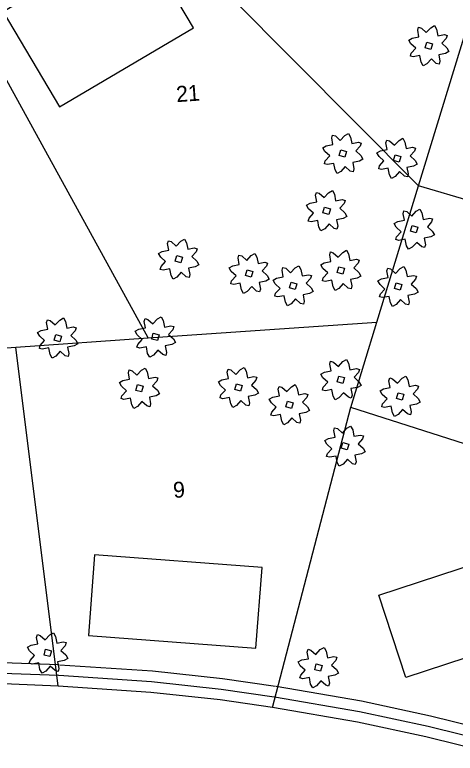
# Model space of a CAD drawing. Extents: x 1810019 to 1811399, y 1074962 to 1076105.
# Drawn here: x 1810473.9 to 1810639.9, y 1075253.3 to 1075531.7 of the extents above; entities that cross this region are included whole.
import ezdxf

# ---------------------------------------------------------------- set-up
doc = ezdxf.new("R2010")
doc.units = 0
for name, color, linetype in [('Environmental-New trees', 7, 'Continuous'), ('Property-Buildings', 7, 'Continuous'), ('Roadway-Land lines', 7, 'Continuous'), ('Roadway-Sidewalks', 7, 'Continuous'), ('Text-Property owner', 7, 'Continuous')]:
    doc.layers.add(name, color=color, linetype=linetype)

msp = doc.modelspace()

# ---------------------------------------------------------------- linework, layer by layer
at = {"layer": 'Environmental-New trees'}
for points in [[(1810623, 1075516.16), (1810623.31, 1075517.24), (1810625, 1075519.1), (1810623.14, 1075520.79), (1810622.36, 1075522.18), (1810623.72, 1075522.94), (1810626.22, 1075523.43), (1810625.75, 1075525.9), (1810626.06, 1075526.99), (1810627.14, 1075526.68), (1810629, 1075524.99), (1810630.69, 1075526.85), (1810632.08, 1075527.63), (1810632.86, 1075526.24), (1810633.33, 1075523.77), (1810635.8, 1075524.24), (1810636.89, 1075523.94), (1810636.52, 1075522.78), (1810634.89, 1075520.99), (1810636.75, 1075519.3), (1810637.53, 1075517.91), (1810636.18, 1075517.15), (1810633.67, 1075516.66), (1810634.14, 1075514.19), (1810633.84, 1075513.1), (1810632.75, 1075513.41), (1810630.89, 1075515.1), (1810629.2, 1075513.24), (1810627.81, 1075512.46), (1810627.03, 1075513.85), (1810626.56, 1075516.32), (1810624.09, 1075515.85)], [(1810629.17, 1075521.43), (1810631.33, 1075520.82), (1810630.72, 1075518.66), (1810628.56, 1075519.27)], [(1810590.59, 1075475.55), (1810590.89, 1075476.63), (1810592.58, 1075478.49), (1810590.72, 1075480.18), (1810589.94, 1075481.57), (1810591.3, 1075482.33), (1810593.8, 1075482.82), (1810593.33, 1075485.29), (1810593.64, 1075486.38), (1810594.72, 1075486.07), (1810596.58, 1075484.38), (1810598.27, 1075486.24), (1810599.66, 1075487.02), (1810600.44, 1075485.63), (1810600.91, 1075483.16), (1810603.38, 1075483.63), (1810604.47, 1075483.33), (1810604.1, 1075482.17), (1810602.47, 1075480.38), (1810604.33, 1075478.69), (1810605.11, 1075477.3), (1810603.76, 1075476.54), (1810601.25, 1075476.05), (1810601.72, 1075473.58), (1810601.42, 1075472.49), (1810600.33, 1075472.8), (1810598.47, 1075474.49), (1810596.78, 1075472.63), (1810595.39, 1075471.85), (1810594.61, 1075473.24), (1810594.14, 1075475.71), (1810591.67, 1075475.24)], [(1810611.04, 1075473.67), (1810611.34, 1075474.75), (1810613.03, 1075476.62), (1810611.17, 1075478.31), (1810610.39, 1075479.7), (1810611.75, 1075480.45), (1810614.25, 1075480.95), (1810613.78, 1075483.42), (1810614.09, 1075484.5), (1810615.17, 1075484.2), (1810617.03, 1075482.5), (1810618.72, 1075484.36), (1810620.11, 1075485.14), (1810620.89, 1075483.75), (1810621.36, 1075481.28), (1810623.83, 1075481.76), (1810624.92, 1075481.45), (1810624.55, 1075480.29), (1810622.92, 1075478.51), (1810624.78, 1075476.81), (1810625.56, 1075475.42), (1810624.21, 1075474.67), (1810621.7, 1075474.17), (1810622.17, 1075471.7), (1810621.87, 1075470.62), (1810620.78, 1075470.92), (1810618.92, 1075472.62), (1810617.23, 1075470.76), (1810615.84, 1075469.98), (1810615.06, 1075471.37), (1810614.59, 1075473.84), (1810612.12, 1075473.37)], [(1810596.75, 1075480.82), (1810598.91, 1075480.21), (1810598.3, 1075478.05), (1810596.14, 1075478.66)], [(1810617.2, 1075478.95), (1810619.36, 1075478.34), (1810618.75, 1075476.17), (1810616.59, 1075476.78)], [(1810584.5, 1075453.94), (1810584.8, 1075455.03), (1810586.5, 1075456.89), (1810584.64, 1075458.58), (1810583.86, 1075459.97), (1810585.21, 1075460.73), (1810587.72, 1075461.22), (1810587.25, 1075463.69), (1810587.55, 1075464.77), (1810588.63, 1075464.47), (1810590.49, 1075462.78), (1810592.19, 1075464.64), (1810593.58, 1075465.42), (1810594.35, 1075464.03), (1810594.83, 1075461.56), (1810597.3, 1075462.03), (1810598.38, 1075461.72), (1810598.01, 1075460.57), (1810596.38, 1075458.78), (1810598.24, 1075457.09), (1810599.02, 1075455.7), (1810597.67, 1075454.94), (1810595.16, 1075454.45), (1810595.64, 1075451.98), (1810595.33, 1075450.89), (1810594.25, 1075451.2), (1810592.39, 1075452.89), (1810590.69, 1075451.03), (1810589.3, 1075450.25), (1810588.53, 1075451.64), (1810588.05, 1075454.11), (1810585.58, 1075453.64)], [(1810590.66, 1075459.22), (1810592.83, 1075458.61), (1810592.22, 1075456.45), (1810590.05, 1075457.06)], [(1810617.5, 1075446.98), (1810617.81, 1075448.06), (1810619.5, 1075449.92), (1810617.64, 1075451.62), (1810616.86, 1075453), (1810618.21, 1075453.76), (1810620.72, 1075454.25), (1810620.25, 1075456.73), (1810620.55, 1075457.81), (1810621.63, 1075457.5), (1810623.5, 1075455.81), (1810625.19, 1075457.67), (1810626.58, 1075458.45), (1810627.36, 1075457.06), (1810627.83, 1075454.59), (1810630.3, 1075455.06), (1810631.38, 1075454.76), (1810631.01, 1075453.6), (1810629.38, 1075451.81), (1810631.25, 1075450.12), (1810632.02, 1075448.73), (1810630.67, 1075447.97), (1810628.16, 1075447.48), (1810628.64, 1075445.01), (1810628.33, 1075443.93), (1810627.25, 1075444.23), (1810625.39, 1075445.92), (1810623.69, 1075444.06), (1810622.31, 1075443.29), (1810621.53, 1075444.67), (1810621.05, 1075447.15), (1810618.58, 1075446.67)], [(1810623.66, 1075452.26), (1810625.83, 1075451.65), (1810625.22, 1075449.48), (1810623.05, 1075450.09)], [(1810528.75, 1075435.71), (1810529.06, 1075436.79), (1810530.75, 1075438.66), (1810528.89, 1075440.35), (1810528.11, 1075441.74), (1810529.46, 1075442.49), (1810531.97, 1075442.99), (1810531.5, 1075445.46), (1810531.8, 1075446.54), (1810532.89, 1075446.24), (1810534.75, 1075444.54), (1810536.44, 1075446.4), (1810537.83, 1075447.18), (1810538.61, 1075445.79), (1810539.08, 1075443.32), (1810541.55, 1075443.8), (1810542.63, 1075443.49), (1810542.27, 1075442.33), (1810540.64, 1075440.55), (1810542.5, 1075438.85), (1810543.27, 1075437.47), (1810541.92, 1075436.71), (1810539.42, 1075436.21), (1810539.89, 1075433.74), (1810539.58, 1075432.66), (1810538.5, 1075432.97), (1810536.64, 1075434.66), (1810534.95, 1075432.8), (1810533.56, 1075432.02), (1810532.78, 1075433.41), (1810532.31, 1075435.88), (1810529.84, 1075435.41)], [(1810589.82, 1075431.46), (1810590.12, 1075432.54), (1810591.82, 1075434.4), (1810589.96, 1075436.1), (1810589.18, 1075437.48), (1810590.53, 1075438.24), (1810593.04, 1075438.74), (1810592.57, 1075441.21), (1810592.87, 1075442.29), (1810593.95, 1075441.99), (1810595.81, 1075440.29), (1810597.51, 1075442.15), (1810598.9, 1075442.93), (1810599.67, 1075441.54), (1810600.15, 1075439.07), (1810602.62, 1075439.54), (1810603.7, 1075439.24), (1810603.33, 1075438.08), (1810601.7, 1075436.29), (1810603.56, 1075434.6), (1810604.34, 1075433.21), (1810602.99, 1075432.46), (1810600.48, 1075431.96), (1810600.95, 1075429.49), (1810600.65, 1075428.41), (1810599.57, 1075428.71), (1810597.71, 1075430.41), (1810596.01, 1075428.55), (1810594.62, 1075427.77), (1810593.85, 1075429.16), (1810593.37, 1075431.63), (1810590.9, 1075431.15)], [(1810534.92, 1075440.99), (1810537.08, 1075440.38), (1810536.47, 1075438.21), (1810534.31, 1075438.82)], [(1810555.31, 1075430.3), (1810555.61, 1075431.38), (1810557.3, 1075433.25), (1810555.44, 1075434.94), (1810554.67, 1075436.33), (1810556.02, 1075437.08), (1810558.52, 1075437.58), (1810558.05, 1075440.05), (1810558.36, 1075441.13), (1810559.44, 1075440.83), (1810561.3, 1075439.13), (1810562.99, 1075440.99), (1810564.38, 1075441.77), (1810565.16, 1075440.38), (1810565.63, 1075437.91), (1810568.11, 1075438.39), (1810569.19, 1075438.08), (1810568.82, 1075436.92), (1810567.19, 1075435.14), (1810569.05, 1075433.44), (1810569.83, 1075432.06), (1810568.48, 1075431.3), (1810565.97, 1075430.8), (1810566.44, 1075428.33), (1810566.14, 1075427.25), (1810565.05, 1075427.55), (1810563.19, 1075429.25), (1810561.5, 1075427.39), (1810560.11, 1075426.61), (1810559.33, 1075428), (1810558.86, 1075430.47), (1810556.39, 1075430)], [(1810571.86, 1075425.64), (1810572.17, 1075426.72), (1810573.86, 1075428.58), (1810572, 1075430.27), (1810571.22, 1075431.66), (1810572.57, 1075432.42), (1810575.08, 1075432.91), (1810574.61, 1075435.38), (1810574.91, 1075436.47), (1810576, 1075436.16), (1810577.86, 1075434.47), (1810579.55, 1075436.33), (1810580.94, 1075437.11), (1810581.72, 1075435.72), (1810582.19, 1075433.25), (1810584.66, 1075433.72), (1810585.74, 1075433.42), (1810585.38, 1075432.26), (1810583.75, 1075430.47), (1810585.61, 1075428.78), (1810586.38, 1075427.39), (1810585.03, 1075426.63), (1810582.53, 1075426.14), (1810583, 1075423.67), (1810582.69, 1075422.59), (1810581.61, 1075422.89), (1810579.75, 1075424.58), (1810578.06, 1075422.72), (1810576.67, 1075421.94), (1810575.89, 1075423.33), (1810575.42, 1075425.8), (1810572.95, 1075425.33)], [(1810595.98, 1075436.74), (1810598.15, 1075436.13), (1810597.54, 1075433.96), (1810595.37, 1075434.57)], [(1810611.41, 1075425.37), (1810611.72, 1075426.46), (1810613.41, 1075428.32), (1810611.55, 1075430.01), (1810610.77, 1075431.4), (1810612.13, 1075432.16), (1810614.63, 1075432.65), (1810614.16, 1075435.12), (1810614.47, 1075436.21), (1810615.55, 1075435.9), (1810617.41, 1075434.21), (1810619.1, 1075436.07), (1810620.49, 1075436.85), (1810621.27, 1075435.46), (1810621.74, 1075432.99), (1810624.21, 1075433.46), (1810625.3, 1075433.15), (1810624.93, 1075432), (1810623.3, 1075430.21), (1810625.16, 1075428.52), (1810625.94, 1075427.13), (1810624.58, 1075426.37), (1810622.08, 1075425.88), (1810622.55, 1075423.41), (1810622.25, 1075422.32), (1810621.16, 1075422.63), (1810619.3, 1075424.32), (1810617.61, 1075422.46), (1810616.22, 1075421.68), (1810615.44, 1075423.07), (1810614.97, 1075425.54), (1810612.5, 1075425.07)], [(1810561.47, 1075435.58), (1810563.64, 1075434.97), (1810563.02, 1075432.8), (1810560.86, 1075433.41)], [(1810578.03, 1075430.91), (1810580.19, 1075430.3), (1810579.58, 1075428.14), (1810577.41, 1075428.75)], [(1810617.58, 1075430.65), (1810619.74, 1075430.04), (1810619.13, 1075427.88), (1810616.97, 1075428.49)], [(1810483.15, 1075405.94), (1810483.45, 1075407.02), (1810485.15, 1075408.88), (1810483.29, 1075410.57), (1810482.51, 1075411.96), (1810483.86, 1075412.72), (1810486.37, 1075413.21), (1810485.89, 1075415.68), (1810486.2, 1075416.77), (1810487.28, 1075416.46), (1810489.14, 1075414.77), (1810490.84, 1075416.63), (1810492.23, 1075417.41), (1810493, 1075416.02), (1810493.48, 1075413.55), (1810495.95, 1075414.02), (1810497.03, 1075413.72), (1810496.66, 1075412.56), (1810495.03, 1075410.77), (1810496.89, 1075409.08), (1810497.67, 1075407.69), (1810496.32, 1075406.93), (1810493.81, 1075406.44), (1810494.28, 1075403.97), (1810493.98, 1075402.88), (1810492.9, 1075403.19), (1810491.03, 1075404.88), (1810489.34, 1075403.02), (1810487.95, 1075402.24), (1810487.18, 1075403.63), (1810486.7, 1075406.1), (1810484.23, 1075405.63)], [(1810519.94, 1075406.36), (1810520.25, 1075407.44), (1810521.94, 1075409.3), (1810520.08, 1075411), (1810519.3, 1075412.39), (1810520.66, 1075413.14), (1810523.16, 1075413.64), (1810522.69, 1075416.11), (1810522.99, 1075417.19), (1810524.08, 1075416.89), (1810525.94, 1075415.19), (1810527.63, 1075417.05), (1810529.02, 1075417.83), (1810529.8, 1075416.44), (1810530.27, 1075413.97), (1810532.74, 1075414.44), (1810533.83, 1075414.14), (1810533.46, 1075412.98), (1810531.83, 1075411.2), (1810533.69, 1075409.5), (1810534.47, 1075408.11), (1810533.11, 1075407.36), (1810530.61, 1075406.86), (1810531.08, 1075404.39), (1810530.77, 1075403.31), (1810529.69, 1075403.61), (1810527.83, 1075405.31), (1810526.14, 1075403.45), (1810524.75, 1075402.67), (1810523.97, 1075404.06), (1810523.5, 1075406.53), (1810521.03, 1075406.06)], [(1810526.11, 1075411.64), (1810528.27, 1075411.03), (1810527.66, 1075408.86), (1810525.5, 1075409.47)], [(1810489.31, 1075411.21), (1810491.48, 1075410.6), (1810490.87, 1075408.44), (1810488.7, 1075409.05)], [(1810589.86, 1075390.25), (1810590.17, 1075391.34), (1810591.86, 1075393.2), (1810590, 1075394.89), (1810589.22, 1075396.28), (1810590.58, 1075397.04), (1810593.08, 1075397.53), (1810592.61, 1075400), (1810592.92, 1075401.08), (1810594, 1075400.78), (1810595.86, 1075399.08), (1810597.55, 1075400.95), (1810598.94, 1075401.72), (1810599.72, 1075400.34), (1810600.19, 1075397.86), (1810602.66, 1075398.34), (1810603.75, 1075398.03), (1810603.38, 1075396.88), (1810601.75, 1075395.09), (1810603.61, 1075393.39), (1810604.39, 1075392.01), (1810603.03, 1075391.25), (1810600.53, 1075390.76), (1810601, 1075388.28), (1810600.7, 1075387.2), (1810599.61, 1075387.51), (1810597.75, 1075389.2), (1810596.06, 1075387.34), (1810594.67, 1075386.56), (1810593.89, 1075387.95), (1810593.42, 1075390.42), (1810590.95, 1075389.95)], [(1810513.95, 1075387.01), (1810514.26, 1075388.09), (1810515.95, 1075389.95), (1810514.09, 1075391.64), (1810513.31, 1075393.03), (1810514.66, 1075393.79), (1810517.17, 1075394.28), (1810516.7, 1075396.75), (1810517, 1075397.84), (1810518.09, 1075397.53), (1810519.95, 1075395.84), (1810521.64, 1075397.7), (1810523.03, 1075398.48), (1810523.81, 1075397.09), (1810524.28, 1075394.62), (1810526.75, 1075395.09), (1810527.83, 1075394.79), (1810527.46, 1075393.63), (1810525.84, 1075391.84), (1810527.7, 1075390.15), (1810528.47, 1075388.76), (1810527.12, 1075388), (1810524.61, 1075387.51), (1810525.09, 1075385.04), (1810524.78, 1075383.95), (1810523.7, 1075384.26), (1810521.84, 1075385.95), (1810520.14, 1075384.09), (1810518.76, 1075383.31), (1810517.98, 1075384.7), (1810517.51, 1075387.17), (1810515.03, 1075386.7)], [(1810551.25, 1075387.29), (1810551.55, 1075388.37), (1810553.25, 1075390.23), (1810551.38, 1075391.93), (1810550.61, 1075393.32), (1810551.96, 1075394.07), (1810554.47, 1075394.57), (1810553.99, 1075397.04), (1810554.3, 1075398.12), (1810555.38, 1075397.82), (1810557.24, 1075396.12), (1810558.94, 1075397.98), (1810560.32, 1075398.76), (1810561.1, 1075397.37), (1810561.57, 1075394.9), (1810564.05, 1075395.37), (1810565.13, 1075395.07), (1810564.76, 1075393.91), (1810563.13, 1075392.13), (1810564.99, 1075390.43), (1810565.77, 1075389.04), (1810564.42, 1075388.29), (1810561.91, 1075387.79), (1810562.38, 1075385.32), (1810562.08, 1075384.24), (1810560.99, 1075384.54), (1810559.13, 1075386.24), (1810557.44, 1075384.38), (1810556.05, 1075383.6), (1810555.27, 1075384.99), (1810554.8, 1075387.46), (1810552.33, 1075386.98)], [(1810596.03, 1075395.53), (1810598.19, 1075394.92), (1810597.58, 1075392.75), (1810595.42, 1075393.36)], [(1810612.18, 1075383.97), (1810612.48, 1075385.05), (1810614.18, 1075386.91), (1810612.32, 1075388.6), (1810611.54, 1075389.99), (1810612.89, 1075390.75), (1810615.4, 1075391.24), (1810614.93, 1075393.71), (1810615.23, 1075394.8), (1810616.31, 1075394.49), (1810618.17, 1075392.8), (1810619.87, 1075394.66), (1810621.26, 1075395.44), (1810622.03, 1075394.05), (1810622.51, 1075391.58), (1810624.98, 1075392.05), (1810626.06, 1075391.74), (1810625.69, 1075390.59), (1810624.06, 1075388.8), (1810625.92, 1075387.11), (1810626.7, 1075385.72), (1810625.35, 1075384.96), (1810622.84, 1075384.47), (1810623.32, 1075382), (1810623.01, 1075380.91), (1810621.93, 1075381.22), (1810620.07, 1075382.91), (1810618.37, 1075381.05), (1810616.98, 1075380.27), (1810616.21, 1075381.66), (1810615.73, 1075384.13), (1810613.26, 1075383.66)], [(1810520.11, 1075392.28), (1810522.28, 1075391.67), (1810521.67, 1075389.51), (1810519.5, 1075390.12)], [(1810557.41, 1075392.57), (1810559.58, 1075391.96), (1810558.97, 1075389.79), (1810556.8, 1075390.4)], [(1810570.45, 1075380.8), (1810570.76, 1075381.88), (1810572.45, 1075383.74), (1810570.59, 1075385.44), (1810569.81, 1075386.83), (1810571.16, 1075387.58), (1810573.67, 1075388.08), (1810573.2, 1075390.55), (1810573.5, 1075391.63), (1810574.59, 1075391.33), (1810576.45, 1075389.63), (1810578.14, 1075391.49), (1810579.53, 1075392.27), (1810580.31, 1075390.88), (1810580.78, 1075388.41), (1810583.25, 1075388.88), (1810584.34, 1075388.58), (1810583.97, 1075387.42), (1810582.34, 1075385.63), (1810584.2, 1075383.94), (1810584.98, 1075382.55), (1810583.62, 1075381.8), (1810581.12, 1075381.3), (1810581.59, 1075378.83), (1810581.28, 1075377.75), (1810580.2, 1075378.05), (1810578.34, 1075379.75), (1810576.65, 1075377.89), (1810575.26, 1075377.11), (1810574.48, 1075378.5), (1810574.01, 1075380.97), (1810571.54, 1075380.49)], [(1810618.34, 1075389.24), (1810620.51, 1075388.63), (1810619.9, 1075386.47), (1810617.73, 1075387.08)], [(1810576.62, 1075386.08), (1810578.78, 1075385.47), (1810578.17, 1075383.3), (1810576.01, 1075383.91)], [(1810591.4, 1075365.19), (1810591.71, 1075366.27), (1810593.4, 1075368.13), (1810591.54, 1075369.82), (1810590.76, 1075371.21), (1810592.11, 1075371.97), (1810594.62, 1075372.46), (1810594.15, 1075374.93), (1810594.45, 1075376.02), (1810595.54, 1075375.71), (1810597.4, 1075374.02), (1810599.09, 1075375.88), (1810600.48, 1075376.66), (1810601.26, 1075375.27), (1810601.73, 1075372.8), (1810604.2, 1075373.27), (1810605.29, 1075372.96), (1810604.92, 1075371.81), (1810603.29, 1075370.02), (1810605.15, 1075368.33), (1810605.93, 1075366.94), (1810604.57, 1075366.18), (1810602.07, 1075365.69), (1810602.54, 1075363.22), (1810602.23, 1075362.13), (1810601.15, 1075362.44), (1810599.29, 1075364.13), (1810597.6, 1075362.27), (1810596.21, 1075361.49), (1810595.43, 1075362.88), (1810594.96, 1075365.35), (1810592.49, 1075364.88)], [(1810597.57, 1075370.46), (1810599.73, 1075369.85), (1810599.12, 1075367.69), (1810596.96, 1075368.3)], [(1810479.37, 1075287.22), (1810479.67, 1075288.31), (1810481.37, 1075290.17), (1810479.5, 1075291.86), (1810478.73, 1075293.25), (1810480.08, 1075294.01), (1810482.59, 1075294.5), (1810482.11, 1075296.97), (1810482.42, 1075298.05), (1810483.5, 1075297.75), (1810485.36, 1075296.06), (1810487.06, 1075297.92), (1810488.44, 1075298.69), (1810489.22, 1075297.31), (1810489.69, 1075294.84), (1810492.17, 1075295.31), (1810493.25, 1075295), (1810492.88, 1075293.85), (1810491.25, 1075292.06), (1810493.11, 1075290.37), (1810493.89, 1075288.98), (1810492.54, 1075288.22), (1810490.03, 1075287.73), (1810490.5, 1075285.25), (1810490.2, 1075284.17), (1810489.11, 1075284.48), (1810487.25, 1075286.17), (1810485.56, 1075284.31), (1810484.17, 1075283.53), (1810483.39, 1075284.92), (1810482.92, 1075287.39), (1810480.45, 1075286.92)], [(1810485.53, 1075292.5), (1810487.7, 1075291.89), (1810487.09, 1075289.72), (1810484.92, 1075290.33)], [(1810581.36, 1075281.69), (1810581.67, 1075282.77), (1810583.36, 1075284.63), (1810581.5, 1075286.32), (1810580.72, 1075287.71), (1810582.07, 1075288.47), (1810584.58, 1075288.96), (1810584.11, 1075291.44), (1810584.41, 1075292.52), (1810585.5, 1075292.21), (1810587.36, 1075290.52), (1810589.05, 1075292.38), (1810590.44, 1075293.16), (1810591.22, 1075291.77), (1810591.69, 1075289.3), (1810594.16, 1075289.77), (1810595.25, 1075289.47), (1810594.88, 1075288.31), (1810593.25, 1075286.52), (1810595.11, 1075284.83), (1810595.89, 1075283.44), (1810594.53, 1075282.68), (1810592.03, 1075282.19), (1810592.5, 1075279.72), (1810592.19, 1075278.64), (1810591.11, 1075278.94), (1810589.25, 1075280.63), (1810587.56, 1075278.77), (1810586.17, 1075278), (1810585.39, 1075279.38), (1810584.92, 1075281.86), (1810582.45, 1075281.38)], [(1810587.53, 1075286.97), (1810589.69, 1075286.36), (1810589.08, 1075284.19), (1810586.92, 1075284.8)]]:
    msp.add_lwpolyline(points, close=True, dxfattribs=at)
at = {"layer": 'Property-Buildings'}
for points in [[(1810469.57, 1075532.8), (1810490.73, 1075496.96), (1810541.25, 1075526.79), (1810520.08, 1075562.63)], [(1810681.82, 1075301.73), (1810621.28, 1075281.84), (1810611.09, 1075312.85), (1810671.63, 1075332.75)], [(1810501.65, 1075297.69), (1810564.77, 1075292.91), (1810567.07, 1075323.3), (1810503.95, 1075328.07)]]:
    msp.add_lwpolyline(points, close=True, dxfattribs=at)
at = {"layer": 'Roadway-Land lines'}
for p, q in [((1810626.09, 1075467.25), (1810506.83, 1075587.28)), ((1810626.09, 1075467.25), (1810654.04, 1075558.89)), ((1810524.22, 1075409.88), (1810449.23, 1075546.24)), ((1810610.4, 1075415.83), (1810626.09, 1075467.25)), ((1810744.49, 1075431.86), (1810626.09, 1075467.25)), ((1810524.22, 1075409.88), (1810610.4, 1075415.83)), ((1810600.6, 1075383.71), (1810610.4, 1075415.83)), ((1810474.35, 1075406.44), (1810524.22, 1075409.88)), ((1810386.99, 1075400.41), (1810474.35, 1075406.44)), ((1810490.22, 1075278.58), (1810474.35, 1075406.44)), ((1810571.04, 1075270.55), (1810600.52, 1075383.73)), ((1810600.6, 1075383.71), (1810600.52, 1075383.73)), ((1810719.05, 1075345.61), (1810600.6, 1075383.71))]:
    msp.add_line(p, q, dxfattribs=at)
for points in [[(1810490.22, 1075278.58), (1810472.68, 1075279.3), (1810446.41, 1075279.48), (1810420.15, 1075278.77), (1810400.57, 1075277.57)], [(1810571.04, 1075270.55), (1810551.24, 1075273.4), (1810525.12, 1075276.26), (1810490.22, 1075278.58)], [(1810653.65, 1075253.31), (1810628.78, 1075259.52), (1810603.1, 1075265.03), (1810571.04, 1075270.55)]]:
    msp.add_lwpolyline(points, dxfattribs=at)
at = {"layer": 'Roadway-Sidewalks'}
for points in [[(1810490.55, 1075286.58), (1810472.87, 1075287.3), (1810446.33, 1075287.48), (1810419.8, 1075286.76), (1810400.08, 1075285.55)], [(1810572.18, 1075278.47), (1810552.24, 1075281.34), (1810525.82, 1075284.23), (1810490.75, 1075286.56)], [(1810490.39, 1075282.58), (1810472.78, 1075283.3), (1810446.37, 1075283.48), (1810419.97, 1075282.76), (1810400.33, 1075281.56)], [(1810571.61, 1075274.51), (1810551.74, 1075277.37), (1810525.47, 1075280.24), (1810490.49, 1075282.57)], [(1810655.59, 1075261.07), (1810630.59, 1075267.32), (1810604.61, 1075272.89), (1810572.4, 1075278.43)], [(1810654.62, 1075257.19), (1810629.69, 1075263.42), (1810603.85, 1075268.96), (1810571.72, 1075274.49)]]:
    msp.add_lwpolyline(points, dxfattribs=at)

# ---------------------------------------------------------------- texts
at = {"layer": 'Text-Property owner'}
for s, p in [('21', (1810534.91, 1075498.77)), ('9', (1810533.77, 1075349.53))]:
    msp.add_text(s, height=6, rotation=3.9478, dxfattribs=at).set_placement(p)

doc.saveas('drawing.dxf')
